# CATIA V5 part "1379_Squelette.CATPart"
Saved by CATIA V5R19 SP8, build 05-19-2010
Part number: Squelette
Publications: "Point.1", "Droite.1", "Droite.2", "Point.2", "Droite.3", "Point.3", "Point.4", "Droite.4", "Point.5", "Point.6", "Point.7", "Droite.5", "Droite.6", "Point.8", "Plan.1"
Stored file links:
  C:\Users\ThinkMotion\Desktop\EU_thinkMotion\iao\IAO_MMS_Groupe3\bblot\bblot\1379_Squelette.CATPart
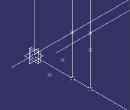
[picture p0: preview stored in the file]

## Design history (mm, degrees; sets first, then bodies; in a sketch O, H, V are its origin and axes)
Body1 (main body)
  Point1: (0, 0, 0)
  Line1: type Normal, RefPoint Point1, RefSkin zx-plane, Start 0, End 20
  Line2: type Normal, RefPoint Point1, RefSkin xy-plane, Start 0, End 20
  Point2: type OnCurve, Support Line1, Length 32
  Line3: type PtDir, RefPoint Point2, Direction Line2, Start 0, End 20
  Point3: type OnCurve, Support Line3, Length 33
  Point4: type OnCurve, Support Line1, RefPoint Point1, Length 47
  Line4: type PtDir, RefPoint Point4, Direction Line2, Start 0, End 20
  Point5: (0, 24, 9), relative to Point1
  Point6: type OnCurve, Support Line4, Length 28
  Point7: type OnCurve, Support Line4, RefPoint Point6, Length 12
  Line5: type Normal, RefPoint Point7, RefSkin yz-plane, Start 0, End 20
  Line6: type Normal, RefPoint Point3, RefSkin yz-plane, Start 0, End 20
  Point8: type OnPlane, Support yz-plane, H 13, V -7, Direction (0, 1, 0)
  Plane1: type Offset, RefPlane yz-plane, Offset 1.5, reversed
